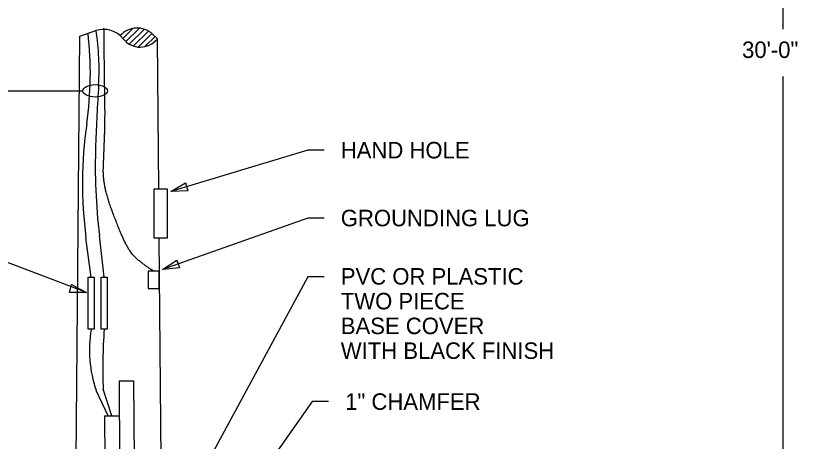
# Model space of a CAD drawing. Extents: x 10112 to 10168, y 10050 to 10179.
# Drawn here: x 10136.31 to 10167.88, y 10101.49 to 10118.69 of the extents above; entities that cross this region are included whole.
import ezdxf

# ---------------------------------------------------------------- set-up
doc = ezdxf.new("R2010")
doc.units = 0
for name, color, linetype in [('G-ANNO-TEXT', 7, 'Continuous'), ('G-DETL-LINE', 7, 'Continuous'), ('G-DETL-OTLN', 7, 'Continuous'), ('G-DETL-PATT', 7, 'Continuous')]:
    doc.layers.add(name, color=color, linetype=linetype)

msp = doc.modelspace()

# ---------------------------------------------------------------- linework, layer by layer
at = {"layer": 'G-ANNO-TEXT'}
for p, q in [((10167.31, 10118.148), (10167.31, 10138.036)), ((10167.31, 10097.305), (10167.31, 10116.237)), ((10135.369, 10115.653), (10139.016, 10115.653)), ((10148.104, 10113.257), (10142.578, 10111.582)), ((10148.771, 10113.257), (10148.104, 10113.257)), ((10148.104, 10110.515), (10142.24, 10108.439)), ((10148.771, 10110.515), (10148.104, 10110.515)), ((10148.104, 10108.141), (10143.31, 10099.275)), ((10148.771, 10108.141), (10148.104, 10108.141)), ((10148.282, 10103.102), (10144.508, 10097.776)), ((10148.948, 10103.102), (10148.282, 10103.102))]:
    msp.add_line(p, q, dxfattribs=at)
for points in [[(10143.264, 10111.616), (10142.578, 10111.582), (10143.168, 10111.935)], [(10142.924, 10108.505), (10142.24, 10108.439), (10142.813, 10108.819)], [(10138.56, 10107.837), (10139.167, 10107.514), (10138.48, 10107.513)]]:
    msp.add_lwpolyline(points, close=True, dxfattribs=at)
msp.add_lwpolyline([(10139.167, 10107.514), (10131.569, 10110.392)], dxfattribs=at)
msp.add_ellipse((10139.516, 10115.653), major_axis=(0.5, 0), ratio=0.5, dxfattribs=at)
at = {"layer": 'G-DETL-LINE'}
for p, q in [((10139.236, 10108.128), (10139.478, 10108.128)), ((10139.236, 10106.024), (10139.236, 10108.128)), ((10139.478, 10108.128), (10139.478, 10106.024)), ((10139.761, 10106.024), (10139.761, 10108.128)), ((10139.761, 10108.128), (10140.004, 10108.128)), ((10140.004, 10108.128), (10140.004, 10106.024)), ((10139.478, 10106.024), (10139.236, 10106.024)), ((10140.004, 10106.024), (10139.761, 10106.024))]:
    msp.add_line(p, q, dxfattribs=at)
for points in [[(10139.357, 10108.128), (10139.146, 10109.722)], [(10139.883, 10108.128), (10139.687, 10109.812)], [(10140.045, 10102.526), (10139.559, 10103.556)], [(10140.185, 10102.53), (10139.842, 10103.597)]]:
    msp.add_lwpolyline(points, dxfattribs=at)
msp.add_lwpolyline([(10142.1, 10108.373), (10141.66, 10108.373), (10141.66, 10107.671), (10142.1, 10107.671)], close=True, dxfattribs=at)
for centre, radius, start, end in [((10125.252, 10116.347), 14.071, 351.7125, 6.6561), ((10129.885, 10116.525), 9.792, 356.2289, 9.1747), ((10215.222, 10110.9), 75.729, 176.22885, 178.04968), ((10155.697, 10111.913), 16.695, 171.7125, 187.5389), ((10164.009, 10112.644), 24.487, 178.0497, 186.6413), ((10144.235, 10105.182), 4.95, 170.1985, 199.1669), ((10160.67, 10104.464), 20.846, 175.7073, 182.3843)]:
    msp.add_arc(centre, radius, start, end, dxfattribs=at)
msp.add_open_spline([(10141.88, 10108.373), (10141.549, 10108.573), (10140.924, 10109.099), (10140.449, 10110.125), (10139.823, 10111.852), (10139.873, 10113.204), (10139.923, 10114.481), (10139.898, 10115.933), (10139.873, 10118.186)], degree=2, dxfattribs=at)
at = {"layer": 'G-DETL-OTLN'}
for p, q in [((10138.725, 10097.812), (10138.896, 10117.867)), ((10142.086, 10111.689), (10142.034, 10117.757)), ((10141.904, 10111.689), (10142.43, 10111.689)), ((10141.904, 10109.706), (10141.904, 10111.689)), ((10142.43, 10111.689), (10142.43, 10109.706)), ((10142.43, 10109.706), (10141.904, 10109.706)), ((10142.204, 10097.812), (10142.103, 10109.706)), ((10140.48, 10103.946), (10141.072, 10103.946)), ((10140.48, 10103.946), (10140.541, 10094.563)), ((10141.072, 10103.946), (10141.132, 10094.563)), ((10139.889, 10102.53), (10140.48, 10102.53)), ((10139.889, 10102.53), (10139.949, 10094.563))]:
    msp.add_line(p, q, dxfattribs=at)
for points in [[(10138.896, 10117.867), (10139.549, 10118.086)], [(10142.034, 10117.757), (10141.833, 10117.944)]]:
    msp.add_lwpolyline(points, dxfattribs=at)
for centre, radius, start, end in [((10139.865, 10117.144), 0.993, 38.0577, 108.5231), ((10141.212, 10117.279), 0.911, 46.9962, 138.5136), ((10141.34, 10118.299), 0.881, 218.0577, 321.992)]:
    msp.add_arc(centre, radius, start, end, dxfattribs=at)
at = {"layer": 'G-DETL-PATT'}
for p, q in [((10140.641, 10117.767), (10141.041, 10118.167)), ((10140.762, 10117.645), (10141.294, 10118.177)), ((10140.903, 10117.545), (10141.49, 10118.132)), ((10141.072, 10117.472), (10141.665, 10118.064)), ((10141.266, 10117.424), (10141.806, 10117.963)), ((10141.524, 10117.44), (10141.935, 10117.851))]:
    msp.add_line(p, q, dxfattribs=at)

# ---------------------------------------------------------------- texts
at = {"layer": 'G-ANNO-TEXT'}
for s, height, p in [('30\'-0"', 0.6667, (10165.645, 10116.98)), ('HAND HOLE', 0.6667, (10149.438, 10112.924)), ('GROUNDING LUG', 0.66667, (10149.438, 10110.182)), ('PVC OR PLASTIC', 0.66667, (10149.438, 10107.826)), ('TWO PIECE', 0.6667, (10149.438, 10106.826)), ('BASE COVER', 0.6667, (10149.438, 10105.826)), ('WITH BLACK FINISH', 0.66667, (10149.438, 10104.826)), ('1" CHAMFER', 0.6667, (10149.615, 10102.768))]:
    msp.add_text(s, height=height, dxfattribs=at).set_placement(p)

doc.saveas('drawing.dxf')
